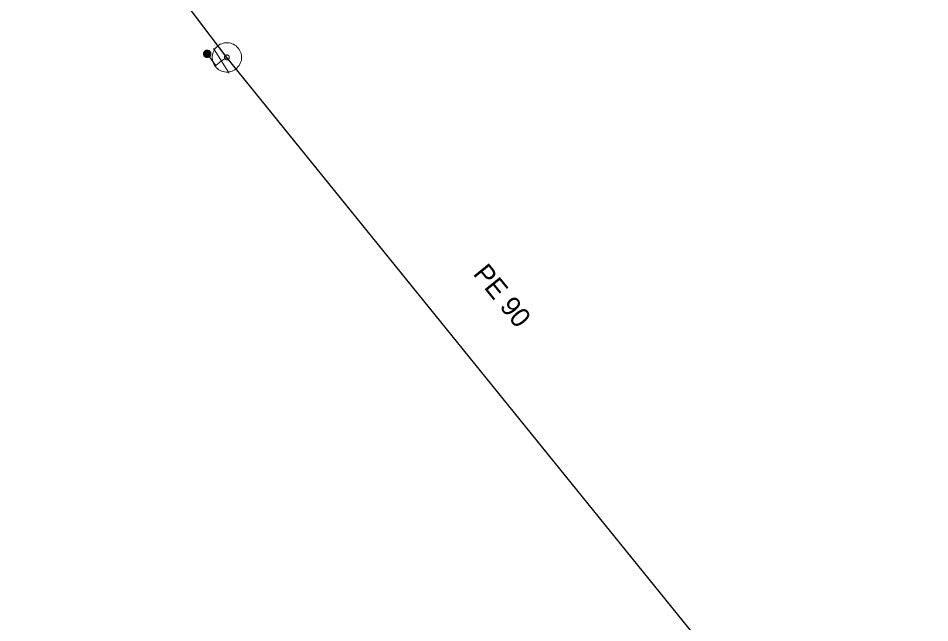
# Model space of a CAD drawing. Extents: x -688296 to -687852, y -973332 to -972816.
# Drawn here: x -688174.53 to -688143.46, y -973073.01 to -973052.38 of the extents above; entities that cross this region are included whole.
import ezdxf
from ezdxf.enums import TextEntityAlignment as Align

# ---------------------------------------------------------------- set-up
doc = ezdxf.new("R2010")
doc.units = 0
doc.header["$LTSCALE"] = 0.27
for name, color, linetype, lineweight in [('1', 7, 'Continuous', 25), ('14', 7, 'Continuous', 13), ('17', 7, 'Continuous', 25), ('34', 7, 'Continuous', 13), ('47', 7, 'Continuous', 13), ('9', 7, 'Continuous', 13)]:
    doc.layers.add(name, color=color, linetype=linetype, lineweight=lineweight)

msp = doc.modelspace()

# ---------------------------------------------------------------- linework, layer by layer
at = {"layer": '14'}
msp.add_line((-688167.42, -973053.719), (-688167.609, -973053.84), dxfattribs=at)
msp.add_lwpolyline([(-688167.609, -973053.84), (-688167.8, -973054), (-688168.092, -973053.598)], dxfattribs=at)
at = {"layer": '17'}
for points in [[(-688167.42, -973053.719), (-688175.149, -973043.51), (-688175.68, -973042.93), (-688189.18, -973023.62), (-688194.239, -973015.879), (-688201.127, -973004.614), (-688201.64, -973003.76), (-688208.85, -972990.539), (-688214.25, -972980.469), (-688218.649, -972971.53), (-688218.84, -972971.059), (-688222.559, -972963.52), (-688226.68, -972954.28), (-688230.09, -972945.899), (-688231.09, -972942.949), (-688233.719, -972935.719), (-688236.539, -972928.36), (-688237.969, -972924.559)], [(-688144.259, -973085.25), (-688144.01, -973085.1), (-688143.456, -973082.873), (-688144.649, -973081.41), (-688145.82, -973079.969), (-688150.12, -973075.1), (-688167.42, -973053.719)]]:
    msp.add_lwpolyline(points, dxfattribs=at)
at = {"layer": '34'}
msp.add_line((-688167.341, -973054.262), (-688167.875, -973053.416), dxfattribs=at)
at = {"layer": '47'}
for points in [[(-688167.734, -973053.33), (-688167.773, -973053.365), (-688167.808, -973053.404), (-688167.838, -973053.446), (-688167.865, -973053.491), (-688167.886, -973053.539), (-688167.902, -973053.589), (-688167.913, -973053.64), (-688167.918, -973053.692), (-688167.918, -973053.744), (-688167.913, -973053.797), (-688167.902, -973053.848), (-688167.886, -973053.898), (-688167.865, -973053.945), (-688167.839, -973053.991), (-688167.808, -973054.033), (-688167.773, -973054.072), (-688167.734, -973054.107), (-688167.691, -973054.138), (-688167.647, -973054.164), (-688167.599, -973054.185), (-688167.549, -973054.201), (-688167.497, -973054.212), (-688167.445, -973054.218), (-688167.393, -973054.218), (-688167.341, -973054.212), (-688167.29, -973054.201), (-688167.24, -973054.185), (-688167.193, -973054.164), (-688167.147, -973054.138), (-688167.105, -973054.107), (-688167.066, -973054.072), (-688167.031, -973054.033), (-688167, -973053.991), (-688166.974, -973053.946), (-688166.953, -973053.898), (-688166.936, -973053.848), (-688166.925, -973053.797), (-688166.92, -973053.745), (-688166.92, -973053.692), (-688166.926, -973053.64), (-688166.937, -973053.589), (-688166.952, -973053.54), (-688166.974, -973053.492), (-688167, -973053.446), (-688167.031, -973053.404), (-688167.066, -973053.365), (-688167.105, -973053.33), (-688167.146, -973053.299), (-688167.192, -973053.273), (-688167.24, -973053.252), (-688167.29, -973053.235), (-688167.34, -973053.225), (-688167.392, -973053.219), (-688167.445, -973053.22), (-688167.498, -973053.225), (-688167.549, -973053.236), (-688167.598, -973053.252), (-688167.646, -973053.273), (-688167.692, -973053.299)], [(-688167.471, -973053.655), (-688167.478, -973053.66), (-688167.483, -973053.667), (-688167.488, -973053.674), (-688167.492, -973053.681), (-688167.496, -973053.689), (-688167.498, -973053.697), (-688167.501, -973053.706), (-688167.502, -973053.714), (-688167.501, -973053.723), (-688167.5, -973053.731), (-688167.499, -973053.74), (-688167.496, -973053.748), (-688167.492, -973053.756), (-688167.489, -973053.763), (-688167.483, -973053.77), (-688167.478, -973053.777), (-688167.471, -973053.782), (-688167.464, -973053.787), (-688167.457, -973053.791), (-688167.449, -973053.795), (-688167.441, -973053.797), (-688167.432, -973053.8), (-688167.424, -973053.801), (-688167.415, -973053.801), (-688167.407, -973053.799), (-688167.398, -973053.798), (-688167.39, -973053.795), (-688167.382, -973053.791), (-688167.375, -973053.788), (-688167.368, -973053.782), (-688167.361, -973053.777), (-688167.356, -973053.77), (-688167.351, -973053.763), (-688167.347, -973053.756), (-688167.343, -973053.748), (-688167.34, -973053.74), (-688167.338, -973053.731), (-688167.337, -973053.723), (-688167.337, -973053.714), (-688167.339, -973053.706), (-688167.34, -973053.697), (-688167.343, -973053.689), (-688167.347, -973053.681), (-688167.35, -973053.674), (-688167.356, -973053.667), (-688167.361, -973053.66), (-688167.368, -973053.655), (-688167.375, -973053.65), (-688167.382, -973053.646), (-688167.39, -973053.642), (-688167.398, -973053.639), (-688167.407, -973053.637), (-688167.415, -973053.636), (-688167.424, -973053.637), (-688167.432, -973053.638), (-688167.441, -973053.639), (-688167.449, -973053.642), (-688167.457, -973053.646), (-688167.464, -973053.649)]]:
    msp.add_lwpolyline(points, close=True, dxfattribs=at)
at = {"layer": '9'}
for points in [[(-688168.218, -973053.598), (-688168.218, -973053.611), (-688168.215, -973053.624), (-688168.213, -973053.637), (-688168.208, -973053.649), (-688168.201, -973053.661), (-688168.195, -973053.672), (-688168.186, -973053.682), (-688168.176, -973053.692), (-688168.166, -973053.7), (-688168.156, -973053.707), (-688168.144, -973053.713), (-688168.132, -973053.718), (-688168.119, -973053.721), (-688168.105, -973053.723), (-688168.093, -973053.725), (-688168.08, -973053.724), (-688168.066, -973053.722), (-688168.054, -973053.719), (-688168.041, -973053.714), (-688168.029, -973053.708), (-688168.019, -973053.701), (-688168.009, -973053.693), (-688167.999, -973053.683), (-688167.99, -973053.673), (-688167.983, -973053.662), (-688167.978, -973053.65), (-688167.973, -973053.638), (-688167.97, -973053.625), (-688167.968, -973053.612), (-688167.965, -973053.599), (-688167.967, -973053.586), (-688167.968, -973053.573), (-688167.972, -973053.56), (-688167.977, -973053.548), (-688167.982, -973053.536), (-688167.99, -973053.525), (-688167.997, -973053.515), (-688168.007, -973053.505), (-688168.017, -973053.497), (-688168.029, -973053.49), (-688168.041, -973053.484), (-688168.053, -973053.479), (-688168.066, -973053.476), (-688168.078, -973053.474), (-688168.092, -973053.473), (-688168.105, -973053.473), (-688168.117, -973053.475), (-688168.13, -973053.478), (-688168.142, -973053.483), (-688168.154, -973053.489), (-688168.166, -973053.496), (-688168.176, -973053.504), (-688168.186, -973053.514), (-688168.193, -973053.524), (-688168.201, -973053.535), (-688168.206, -973053.547), (-688168.212, -973053.559), (-688168.215, -973053.572), (-688168.217, -973053.585)], [(-688168.198, -973053.598), (-688168.198, -973053.609), (-688168.196, -973053.62), (-688168.193, -973053.631), (-688168.19, -973053.641), (-688168.184, -973053.651), (-688168.179, -973053.66), (-688168.171, -973053.669), (-688168.164, -973053.677), (-688168.154, -973053.684), (-688168.146, -973053.69), (-688168.136, -973053.695), (-688168.125, -973053.699), (-688168.115, -973053.702), (-688168.103, -973053.705), (-688168.093, -973053.705), (-688168.081, -973053.705), (-688168.071, -973053.703), (-688168.059, -973053.7), (-688168.049, -973053.696), (-688168.039, -973053.691), (-688168.031, -973053.685), (-688168.022, -973053.678), (-688168.014, -973053.67), (-688168.007, -973053.661), (-688168, -973053.652), (-688167.995, -973053.642), (-688167.992, -973053.632), (-688167.989, -973053.621), (-688167.987, -973053.61), (-688167.985, -973053.599), (-688167.985, -973053.588), (-688167.987, -973053.577), (-688167.99, -973053.566), (-688167.995, -973053.556), (-688168, -973053.546), (-688168.005, -973053.537), (-688168.012, -973053.528), (-688168.021, -973053.52), (-688168.029, -973053.513), (-688168.039, -973053.507), (-688168.049, -973053.502), (-688168.058, -973053.498), (-688168.07, -973053.495), (-688168.08, -973053.493), (-688168.092, -973053.493), (-688168.103, -973053.492), (-688168.114, -973053.494), (-688168.125, -973053.497), (-688168.134, -973053.501), (-688168.144, -973053.506), (-688168.154, -973053.512), (-688168.163, -973053.519), (-688168.171, -973053.527), (-688168.178, -973053.536), (-688168.183, -973053.545), (-688168.188, -973053.555), (-688168.193, -973053.565), (-688168.196, -973053.576), (-688168.198, -973053.587)], [(-688168.179, -973053.598), (-688168.179, -973053.607), (-688168.178, -973053.616), (-688168.174, -973053.625), (-688168.171, -973053.633), (-688168.168, -973053.641), (-688168.163, -973053.649), (-688168.156, -973053.656), (-688168.151, -973053.662), (-688168.144, -973053.668), (-688168.136, -973053.673), (-688168.127, -973053.677), (-688168.12, -973053.68), (-688168.11, -973053.683), (-688168.102, -973053.684), (-688168.093, -973053.686), (-688168.083, -973053.685), (-688168.075, -973053.684), (-688168.066, -973053.681), (-688168.058, -973053.678), (-688168.049, -973053.674), (-688168.041, -973053.669), (-688168.034, -973053.663), (-688168.029, -973053.657), (-688168.022, -973053.65), (-688168.017, -973053.642), (-688168.014, -973053.634), (-688168.011, -973053.626), (-688168.007, -973053.617), (-688168.007, -973053.608), (-688168.004, -973053.599), (-688168.005, -973053.59), (-688168.007, -973053.581), (-688168.009, -973053.572), (-688168.012, -973053.564), (-688168.017, -973053.556), (-688168.022, -973053.548), (-688168.027, -973053.541), (-688168.034, -973053.535), (-688168.041, -973053.529), (-688168.049, -973053.524), (-688168.056, -973053.52), (-688168.065, -973053.517), (-688168.073, -973053.514), (-688168.083, -973053.513), (-688168.092, -973053.512), (-688168.1, -973053.512), (-688168.11, -973053.513), (-688168.119, -973053.516), (-688168.127, -973053.519), (-688168.134, -973053.523), (-688168.142, -973053.528), (-688168.149, -973053.534), (-688168.156, -973053.54), (-688168.161, -973053.547), (-688168.166, -973053.555), (-688168.171, -973053.563), (-688168.174, -973053.571), (-688168.176, -973053.58), (-688168.178, -973053.589)], [(-688168.159, -973053.598), (-688168.159, -973053.605), (-688168.157, -973053.612), (-688168.156, -973053.619), (-688168.154, -973053.625), (-688168.151, -973053.631), (-688168.147, -973053.637), (-688168.142, -973053.643), (-688168.137, -973053.648), (-688168.132, -973053.652), (-688168.125, -973053.656), (-688168.12, -973053.659), (-688168.114, -973053.662), (-688168.107, -973053.663), (-688168.1, -973053.666), (-688168.093, -973053.666), (-688168.085, -973053.666), (-688168.078, -973053.664), (-688168.071, -973053.663), (-688168.066, -973053.66), (-688168.058, -973053.657), (-688168.054, -973053.653), (-688168.048, -973053.649), (-688168.043, -973053.644), (-688168.039, -973053.638), (-688168.034, -973053.632), (-688168.031, -973053.626), (-688168.029, -973053.62), (-688168.027, -973053.613), (-688168.026, -973053.606), (-688168.024, -973053.599), (-688168.024, -973053.592), (-688168.026, -973053.585), (-688168.027, -973053.578), (-688168.031, -973053.572), (-688168.034, -973053.565), (-688168.038, -973053.56), (-688168.041, -973053.554), (-688168.046, -973053.549), (-688168.053, -973053.545), (-688168.058, -973053.541), (-688168.065, -973053.538), (-688168.071, -973053.535), (-688168.078, -973053.533), (-688168.085, -973053.532), (-688168.092, -973053.532), (-688168.098, -973053.532), (-688168.105, -973053.532), (-688168.112, -973053.534), (-688168.119, -973053.537), (-688168.125, -973053.54), (-688168.13, -973053.544), (-688168.137, -973053.548), (-688168.142, -973053.553), (-688168.146, -973053.559), (-688168.149, -973053.564), (-688168.152, -973053.571), (-688168.156, -973053.577), (-688168.156, -973053.584), (-688168.159, -973053.591)], [(-688168.139, -973053.598), (-688168.139, -973053.603), (-688168.139, -973053.608), (-688168.137, -973053.613), (-688168.136, -973053.617), (-688168.134, -973053.622), (-688168.13, -973053.626), (-688168.127, -973053.629), (-688168.124, -973053.633), (-688168.12, -973053.636), (-688168.117, -973053.639), (-688168.112, -973053.641), (-688168.107, -973053.643), (-688168.103, -973053.644), (-688168.098, -973053.646), (-688168.093, -973053.646), (-688168.088, -973053.646), (-688168.083, -973053.645), (-688168.078, -973053.644), (-688168.073, -973053.642), (-688168.068, -973053.64), (-688168.065, -973053.637), (-688168.061, -973053.634), (-688168.058, -973053.63), (-688168.054, -973053.627), (-688168.051, -973053.623), (-688168.049, -973053.618), (-688168.048, -973053.614), (-688168.046, -973053.609), (-688168.046, -973053.604), (-688168.044, -973053.599), (-688168.044, -973053.594), (-688168.046, -973053.589), (-688168.046, -973053.584), (-688168.049, -973053.58), (-688168.051, -973053.575), (-688168.054, -973053.571), (-688168.056, -973053.567), (-688168.059, -973053.564), (-688168.063, -973053.561), (-688168.068, -973053.558), (-688168.073, -973053.556), (-688168.076, -973053.554), (-688168.081, -973053.553), (-688168.087, -973053.552), (-688168.092, -973053.552), (-688168.097, -973053.552), (-688168.102, -973053.553), (-688168.107, -973053.553), (-688168.11, -973053.555), (-688168.115, -973053.557), (-688168.12, -973053.56), (-688168.122, -973053.563), (-688168.127, -973053.566), (-688168.129, -973053.57), (-688168.132, -973053.574), (-688168.134, -973053.579), (-688168.137, -973053.583), (-688168.137, -973053.588), (-688168.139, -973053.593)], [(-688168.119, -973053.598), (-688168.119, -973053.601), (-688168.12, -973053.604), (-688168.119, -973053.606), (-688168.117, -973053.609), (-688168.117, -973053.612), (-688168.115, -973053.614), (-688168.112, -973053.616), (-688168.11, -973053.618), (-688168.108, -973053.62), (-688168.107, -973053.622), (-688168.103, -973053.624), (-688168.1, -973053.625), (-688168.098, -973053.625), (-688168.095, -973053.626), (-688168.093, -973053.626), (-688168.09, -973053.626), (-688168.087, -973053.626), (-688168.083, -973053.625), (-688168.081, -973053.624), (-688168.078, -973053.623), (-688168.076, -973053.621), (-688168.073, -973053.619), (-688168.071, -973053.617), (-688168.071, -973053.615), (-688168.068, -973053.613), (-688168.068, -973053.61), (-688168.066, -973053.607), (-688168.066, -973053.605), (-688168.065, -973053.602), (-688168.063, -973053.599), (-688168.065, -973053.596), (-688168.065, -973053.593), (-688168.066, -973053.59), (-688168.066, -973053.588), (-688168.068, -973053.585), (-688168.07, -973053.583), (-688168.071, -973053.58), (-688168.073, -973053.578), (-688168.076, -973053.577), (-688168.078, -973053.575), (-688168.08, -973053.574), (-688168.083, -973053.573), (-688168.085, -973053.572), (-688168.088, -973053.572), (-688168.092, -973053.571), (-688168.095, -973053.572), (-688168.098, -973053.571), (-688168.1, -973053.573), (-688168.103, -973053.573), (-688168.105, -973053.574), (-688168.107, -973053.576), (-688168.11, -973053.577), (-688168.112, -973053.579), (-688168.114, -973053.582), (-688168.115, -973053.584), (-688168.117, -973053.587), (-688168.117, -973053.589), (-688168.119, -973053.592), (-688168.119, -973053.595)], [(-688168.1, -973053.598), (-688168.1, -973053.6), (-688168.1, -973053.6), (-688168.098, -973053.6), (-688168.098, -973053.602), (-688168.1, -973053.603), (-688168.098, -973053.603), (-688168.098, -973053.603), (-688168.098, -973053.605), (-688168.098, -973053.605), (-688168.097, -973053.606), (-688168.095, -973053.606), (-688168.095, -973053.606), (-688168.095, -973053.607), (-688168.093, -973053.607), (-688168.093, -973053.607), (-688168.092, -973053.607), (-688168.09, -973053.607), (-688168.09, -973053.606), (-688168.09, -973053.606), (-688168.088, -973053.606), (-688168.088, -973053.605), (-688168.088, -973053.605), (-688168.087, -973053.604), (-688168.087, -973053.604), (-688168.085, -973053.603), (-688168.085, -973053.602), (-688168.083, -973053.601), (-688168.083, -973053.601), (-688168.083, -973053.6), (-688168.083, -973053.599), (-688168.083, -973053.598), (-688168.083, -973053.597), (-688168.083, -973053.597), (-688168.085, -973053.596), (-688168.085, -973053.595), (-688168.085, -973053.594), (-688168.085, -973053.594), (-688168.087, -973053.593), (-688168.087, -973053.593), (-688168.088, -973053.592), (-688168.088, -973053.592), (-688168.09, -973053.591), (-688168.09, -973053.591), (-688168.09, -973053.591), (-688168.092, -973053.591), (-688168.093, -973053.591), (-688168.093, -973053.591), (-688168.093, -973053.591), (-688168.095, -973053.592), (-688168.095, -973053.591), (-688168.097, -973053.593), (-688168.097, -973053.593), (-688168.098, -973053.593), (-688168.098, -973053.593), (-688168.098, -973053.595), (-688168.098, -973053.596), (-688168.098, -973053.597), (-688168.1, -973053.597), (-688168.1, -973053.598)]]:
    msp.add_lwpolyline(points, close=True, dxfattribs=at)

# ---------------------------------------------------------------- texts
at = {"layer": '1'}
msp.add_text('PE 90 ', height=0.6667, rotation=309, dxfattribs=at).set_placement((-688158.2108, -973062.1498), align=Align.CENTER)
msp.add_text('PE 90 ', height=0.6667, rotation=309, dxfattribs=at).set_placement((-688158.2108, -973062.1498), align=Align.CENTER)
msp.add_text('PE 90 ', height=0.6667, rotation=309, dxfattribs=at).set_placement((-688158.2108, -973062.1498), align=Align.CENTER)
msp.add_text('PE 90 ', height=0.6667, rotation=309, dxfattribs=at).set_placement((-688158.2108, -973062.1498), align=Align.CENTER)
msp.add_text('PE 90 ', height=0.6667, rotation=309, dxfattribs=at).set_placement((-688158.2108, -973062.1498), align=Align.CENTER)

doc.saveas('drawing.dxf')
